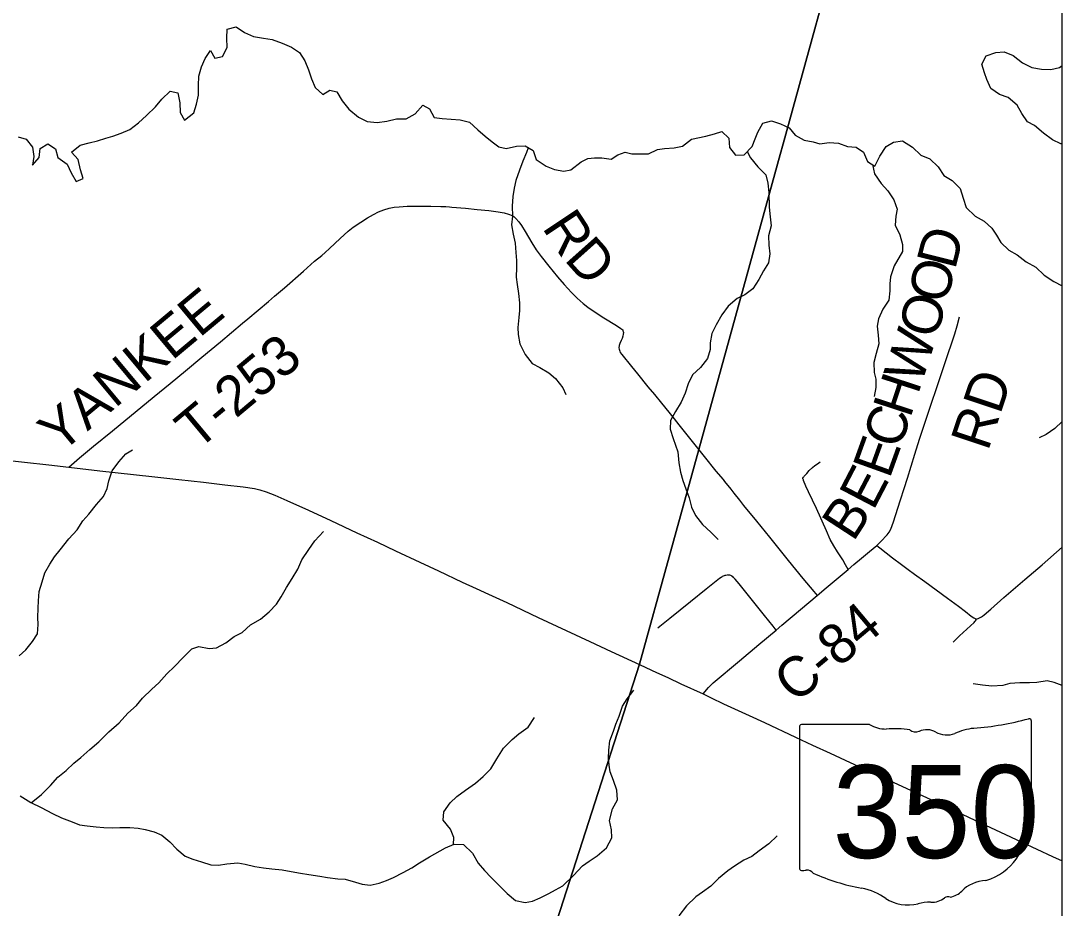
# Model space of a CAD drawing. Extents: x 0 to 34, y 0 to 22.
# Drawn here: x 22.483 to 23.962, y 16.521 to 17.781 of the extents above; entities that cross this region are included whole.
import ezdxf

# ---------------------------------------------------------------- set-up
doc = ezdxf.new("R2010")
doc.units = 0
for name, color, linetype in [('GM_X_Corporation', 7, 'Continuous'), ('GM_X_County_Road', 7, 'Continuous'), ('GM_X_County_Road_Text', 7, 'Continuous'), ('GM_X_Major_Lake', 7, 'Continuous'), ('GM_X_Minor_River', 7, 'Continuous'), ('GM_X_State_Location', 7, 'Continuous'), ('GM_X_State_Route', 7, 'Continuous'), ('GM_X_State_Shield', 7, 'Continuous'), ('GM_X_Township_Road', 7, 'Continuous'), ('GM_X_Township_Road_Text', 7, 'Continuous')]:
    doc.layers.add(name, color=color, linetype=linetype)

msp = doc.modelspace()

# ---------------------------------------------------------------- linework, layer by layer
at = {"layer": 'GM_X_Corporation'}
for points in [[(17.597, 14.3059), (23.9625, 14.3059), (23.9625, 21.1059), (18.23, 21.1059), (18.203, 20.7746), (18.1731, 20.4696), (18.0879, 19.5959), (18.0387, 19.0962), (17.9672, 18.2605), (17.8718, 17.2256), (17.7834, 16.317), (17.7373, 15.7617), (17.7239, 15.6245), (17.6136, 14.4601)], [(22.6629, 14.3059), (23.9625, 14.3059), (23.9625, 18.7666), (23.8567, 18.7798), (23.8507, 18.7519), (23.7107, 18.1304), (23.6615, 17.9524), (23.566, 17.6066), (23.5619, 17.5912), (23.4462, 17.1725), (23.362, 16.8676), (23.1639, 16.2517), (23.0409, 15.7041), (22.7103, 14.4966)]]:
    msp.add_lwpolyline(points, close=True, dxfattribs=at)
msp.add_lwpolyline([(23.1639, 16.2517), (23.362, 16.8676), (23.4462, 17.1725), (23.5619, 17.5912), (23.566, 17.6066), (23.6615, 17.9524), (23.7107, 18.1304), (23.8507, 18.7519), (23.8567, 18.7798), (23.8372, 18.7818), (22.8728, 18.8666), (22.8523, 19.0143), (22.5453, 19.0171), (22.4736, 19.0897), (21.6862, 19.7442)], dxfattribs=at)
at = {"layer": 'GM_X_County_Road'}
for points in [[(23.6991, 17.0361), (23.705, 17.0416), (23.7138, 17.0511), (23.7167, 17.055), (23.7189, 17.0593), (23.7228, 17.0697), (23.7293, 17.0891), (23.7329, 17.101), (23.7379, 17.117), (23.7426, 17.1318), (23.7531, 17.1656), (23.7599, 17.187), (23.7693, 17.2153), (23.7772, 17.2396), (23.7836, 17.2576), (23.7959, 17.2943), (23.8099, 17.3364), (23.8135, 17.348), (23.8169, 17.3606)], [(23.6584, 17.0021), (23.6667, 17.0091), (23.6777, 17.0182), (23.6886, 17.0275), (23.6991, 17.0361)], [(23.6145, 16.9653), (23.6271, 16.9759), (23.65, 16.9951), (23.6584, 17.0021)], [(23.5561, 16.9161), (23.5644, 16.9231), (23.5906, 16.9451), (23.6145, 16.9653)], [(23.4524, 16.8256), (23.4601, 16.8346), (23.467, 16.841), (23.504, 16.8723), (23.5315, 16.8956), (23.5561, 16.9161)]]:
    msp.add_lwpolyline(points, dxfattribs=at)
at = {"layer": 'GM_X_Major_Lake'}
for points in [[(22.4794, 17.6161), (22.491, 17.6128), (22.5001, 17.6015), (22.5017, 17.5882), (22.4998, 17.5761), (22.5096, 17.5868), (22.5111, 17.5997), (22.5219, 17.6066), (22.5327, 17.5995), (22.5361, 17.5869), (22.5491, 17.5774), (22.5548, 17.5651), (22.562, 17.5528), (22.572, 17.5574), (22.5682, 17.5697), (22.5648, 17.5842), (22.5556, 17.5947), (22.5677, 17.6046), (22.5803, 17.6076), (22.5925, 17.6107), (22.6043, 17.6142), (22.6139, 17.6173), (22.6257, 17.6216), (22.638, 17.6269), (22.6504, 17.636), (22.6617, 17.6467), (22.6749, 17.6589), (22.6839, 17.67), (22.6956, 17.6811), (22.7065, 17.6789), (22.7092, 17.6648), (22.7095, 17.6511), (22.7157, 17.6399), (22.7292, 17.6506), (22.733, 17.6626), (22.7356, 17.6754), (22.7356, 17.6891), (22.736, 17.7023), (22.7398, 17.7155), (22.7454, 17.7275), (22.753, 17.7387), (22.7591, 17.7279), (22.7698, 17.7302), (22.7766, 17.7433), (22.7762, 17.7566), (22.7766, 17.7691), (22.7892, 17.7726), (22.8011, 17.7647), (22.8138, 17.759), (22.8281, 17.7563), (22.8402, 17.7545), (22.8548, 17.7495), (22.8679, 17.7438), (22.8794, 17.7363), (22.887, 17.7243), (22.892, 17.7113), (22.8961, 17.6987), (22.9015, 17.6864), (22.9122, 17.6762), (22.9222, 17.6828), (22.9324, 17.6802), (22.9396, 17.6675), (22.9495, 17.6558), (22.9631, 17.6441), (22.9755, 17.638), (22.9894, 17.6365), (23.0035, 17.6384), (23.0169, 17.6418), (23.0309, 17.6418), (23.0436, 17.6491), (23.0542, 17.6613), (23.0639, 17.6561), (23.0703, 17.6438), (23.082, 17.6423)], [(23.9625, 17.6062), (23.9606, 17.6066), (23.9486, 17.6122), (23.936, 17.6217), (23.9231, 17.6323), (23.9134, 17.6378), (23.905, 17.6495), (23.8985, 17.6614), (23.886, 17.672), (23.8736, 17.6765), (23.8613, 17.6848), (23.8553, 17.6979), (23.8521, 17.7074), (23.8483, 17.7197), (23.8547, 17.7313), (23.8681, 17.7362), (23.8799, 17.737), (23.893, 17.7317), (23.9063, 17.7215), (23.9194, 17.7147), (23.9333, 17.7124), (23.9462, 17.7117), (23.9588, 17.7147), (23.9625, 17.7174)], [(23.082, 17.6423), (23.0945, 17.6416), (23.1074, 17.6405), (23.1205, 17.6371), (23.1327, 17.6261), (23.1427, 17.6175), (23.1527, 17.6092), (23.1623, 17.6021), (23.1729, 17.5996), (23.1874, 17.6033), (23.1999, 17.6034), (23.211, 17.597), (23.2156, 17.5843), (23.2297, 17.5745), (23.2413, 17.57), (23.2545, 17.5677), (23.2648, 17.5697), (23.2791, 17.5807), (23.2887, 17.5854), (23.2982, 17.5866), (23.3085, 17.5863), (23.3217, 17.5844), (23.3313, 17.5906), (23.3417, 17.5945), (23.3514, 17.5923), (23.3647, 17.592), (23.3749, 17.5924), (23.3876, 17.5982), (23.3975, 17.5998), (23.4112, 17.6005), (23.423, 17.6033), (23.4358, 17.6131), (23.4563, 17.6171), (23.4689, 17.6206), (23.4789, 17.6237), (23.4888, 17.6143), (23.49, 17.6014), (23.4987, 17.5902), (23.5109, 17.5906), (23.5222, 17.6028), (23.5263, 17.6133), (23.53, 17.6231), (23.5372, 17.6357), (23.5494, 17.6392), (23.5625, 17.635), (23.5745, 17.629), (23.5833, 17.6185), (23.5959, 17.6114), (23.6088, 17.6091), (23.6185, 17.6066), (23.6315, 17.6085), (23.6447, 17.6074), (23.6578, 17.6024), (23.6699, 17.6017), (23.6803, 17.5946), (23.686, 17.5815), (23.6964, 17.5748), (23.7033, 17.589), (23.7127, 17.6024), (23.7228, 17.6086), (23.7357, 17.6105), (23.7498, 17.6018), (23.7616, 17.5905), (23.7744, 17.5852), (23.7865, 17.5738), (23.7945, 17.5615), (23.8061, 17.5543), (23.8175, 17.543), (23.822, 17.5292), (23.8262, 17.5158), (23.8391, 17.5037), (23.8518, 17.4965), (23.8628, 17.4867), (23.8694, 17.4767), (23.8755, 17.4663), (23.8869, 17.4553), (23.8985, 17.4489), (23.9115, 17.4387), (23.9249, 17.4311), (23.9371, 17.4198), (23.9508, 17.4107), (23.9625, 17.405)]]:
    msp.add_lwpolyline(points, dxfattribs=at)
at = {"layer": 'GM_X_Minor_River'}
for points in [[(23.2041, 17.6009), (23.2018, 17.594), (23.1966, 17.5816), (23.1918, 17.5688), (23.1866, 17.5541), (23.1841, 17.5435), (23.1823, 17.5314), (23.1813, 17.5181), (23.1817, 17.5037), (23.1804, 17.4912), (23.1827, 17.4779), (23.1855, 17.4653), (23.1867, 17.452), (23.1873, 17.4406), (23.1874, 17.4308), (23.1872, 17.4171), (23.1885, 17.4065), (23.1901, 17.3939), (23.1917, 17.3806), (23.1915, 17.3696), (23.1909, 17.3598), (23.1891, 17.3454), (23.1897, 17.3355), (23.192, 17.3222), (23.1997, 17.3072), (23.2097, 17.2945), (23.2205, 17.289), (23.2332, 17.2811), (23.2429, 17.2734), (23.2533, 17.2599), (23.2576, 17.2503)], [(23.5153, 17.5954), (23.5199, 17.5866), (23.5302, 17.5738), (23.5417, 17.5626), (23.5445, 17.5504), (23.5457, 17.5371), (23.5461, 17.5166), (23.5477, 17.5029), (23.5493, 17.49), (23.5453, 17.476), (23.5457, 17.4627), (23.5474, 17.4502), (23.5456, 17.4373), (23.5382, 17.4261), (23.5315, 17.4137), (23.5229, 17.4006), (23.5117, 17.3921), (23.501, 17.387), (23.4883, 17.3759), (23.4793, 17.3635), (23.4711, 17.3496), (23.4647, 17.3369), (23.4626, 17.324), (23.4624, 17.3145), (23.4587, 17.3017), (23.449, 17.289), (23.4374, 17.2782), (23.4311, 17.2655), (23.427, 17.2523), (23.4214, 17.2395), (23.4132, 17.2264), (23.4061, 17.2136), (23.4055, 17.2011), (23.4098, 17.1881), (23.4168, 17.1691)], [(23.6933, 17.5769), (23.6959, 17.5637), (23.7055, 17.5499), (23.7148, 17.5395), (23.7236, 17.5268), (23.7279, 17.5138), (23.7262, 17.5039), (23.7251, 17.4911), (23.732, 17.4773), (23.7359, 17.4635), (23.7357, 17.4537), (23.7239, 17.433), (23.7187, 17.4176), (23.7177, 17.4074), (23.7179, 17.3975), (23.7161, 17.3846), (23.7079, 17.3715), (23.7016, 17.358), (23.6995, 17.3474), (23.7011, 17.3345), (23.702, 17.3223), (23.6983, 17.3087), (23.695, 17.2959), (23.6955, 17.2818), (23.6979, 17.2723), (23.698, 17.2602), (23.6955, 17.2477)], [(23.9625, 17.2122), (23.9522, 17.202), (23.9399, 17.1935), (23.9296, 17.1888)], [(22.481, 16.8793), (22.4906, 16.8879), (22.5002, 16.8999), (22.5072, 16.9108), (22.5082, 16.9241), (22.5076, 16.934), (22.5081, 16.9473), (22.5087, 16.9575), (22.5096, 16.9708), (22.5136, 16.9844), (22.5176, 16.9972), (22.5246, 17.0097), (22.5312, 17.0198), (22.5393, 17.03), (22.5517, 17.0454), (22.5632, 17.0581), (22.5717, 17.0709), (22.5798, 17.0807), (22.5907, 17.0942), (22.6007, 17.1058), (22.6062, 17.1171), (22.6086, 17.1281), (22.6133, 17.1421), (22.6226, 17.1549), (22.6327, 17.1661), (22.6422, 17.1717)], [(23.4168, 17.1691), (23.4181, 17.1535), (23.4206, 17.1402), (23.4238, 17.1284), (23.4278, 17.1166), (23.4325, 17.1036), (23.4362, 17.0906), (23.4417, 17.0788), (23.4517, 17.0658), (23.4637, 17.055), (23.4738, 17.0446)], [(22.498, 16.6709), (22.513, 16.6826), (22.5257, 16.6953), (22.5361, 16.7073), (22.5476, 16.7167), (22.5588, 16.7268), (22.5684, 16.735), (22.5814, 16.7466), (22.5941, 16.7574), (22.6083, 16.7713), (22.6233, 16.7844), (22.6356, 16.7982), (22.6479, 16.8091), (22.6564, 16.8192), (22.6695, 16.8319), (22.6795, 16.8413), (22.6907, 16.8537), (22.7018, 16.8645), (22.7141, 16.8769), (22.7265, 16.8896), (22.736, 16.8929), (22.7507, 16.8897), (22.7614, 16.891), (22.7747, 16.8977), (22.7866, 16.907), (22.7977, 16.9126), (22.8096, 16.9234), (22.8238, 16.9316), (22.836, 16.942), (22.8464, 16.9529), (22.853, 16.9631), (22.8608, 16.9766), (22.8686, 16.9894), (22.8767, 17.0026), (22.8826, 17.0158), (22.8923, 17.0305), (22.9008, 17.0425), (22.9132, 17.056)], [(23.9625, 16.8375), (23.9509, 16.8414), (23.941, 16.8438), (23.9266, 16.8414), (23.9163, 16.8411), (23.9023, 16.8413), (23.8883, 16.84), (23.878, 16.8371), (23.8628, 16.8365), (23.8492, 16.8379), (23.8363, 16.8396)], [(23.0496, 16.5853), (23.0638, 16.5942), (23.0867, 16.6068), (23.0989, 16.612), (23.1122, 16.6114), (23.1249, 16.5991), (23.133, 16.5849), (23.142, 16.5746), (23.1513, 16.5649), (23.1611, 16.5553), (23.1741, 16.5419), (23.1861, 16.5322), (23.1997, 16.5294), (23.2104, 16.5311), (23.2211, 16.5359), (23.2333, 16.5422), (23.2428, 16.547), (23.2532, 16.5529), (23.2682, 16.5675), (23.2813, 16.5814), (23.2908, 16.5877), (23.3019, 16.5955), (23.3154, 16.6067), (23.3228, 16.6211), (23.3226, 16.6325), (23.3197, 16.6458), (23.3238, 16.6621), (23.3308, 16.6749), (23.3298, 16.6885), (23.3251, 16.7023), (23.3207, 16.7149), (23.319, 16.7244), (23.318, 16.7339), (23.3185, 16.7456), (23.3199, 16.7589), (23.325, 16.7725), (23.3285, 16.7823), (23.3333, 16.7937), (23.338, 16.808), (23.3446, 16.8182), (23.3543, 16.8306)], [(23.098, 16.6116), (23.0983, 16.6215), (23.0936, 16.6333), (23.0831, 16.646), (23.0841, 16.6581), (23.093, 16.6709), (23.1026, 16.6795), (23.1152, 16.6888), (23.1294, 16.6985), (23.1401, 16.7082), (23.1509, 16.7191), (23.1595, 16.7334), (23.1688, 16.7484), (23.1811, 16.7604), (23.1907, 16.7686), (23.2041, 16.7783), (23.213, 16.7919)], [(22.4827, 16.6807), (22.4977, 16.671), (22.5124, 16.664), (22.5282, 16.6554), (22.5413, 16.6492), (22.5564, 16.6437), (22.5666, 16.6397), (22.5776, 16.6381), (22.5904, 16.6364), (22.6014, 16.6358), (22.6136, 16.6353), (22.6242, 16.6359), (22.6382, 16.6357), (22.6503, 16.6348), (22.6602, 16.6328), (22.6726, 16.6296), (22.6836, 16.6248), (22.6952, 16.6152), (22.7049, 16.6048), (22.7169, 16.5952), (22.7278, 16.5908), (22.7399, 16.5869), (22.7531, 16.5829), (22.7641, 16.582), (22.7759, 16.5841), (22.7914, 16.5854), (22.802, 16.5837), (22.8156, 16.5805), (22.8281, 16.5785), (22.8398, 16.5772), (22.8546, 16.5754), (22.8675, 16.573), (22.8807, 16.5709), (22.8924, 16.5689), (22.9083, 16.5667), (22.9189, 16.5647), (22.9337, 16.563), (22.9439, 16.5621), (22.9586, 16.5581), (22.9684, 16.5553), (22.9794, 16.5536), (22.9923, 16.5565), (23.0026, 16.5605), (23.0126, 16.5649), (23.0263, 16.5716), (23.0389, 16.5782), (23.0496, 16.5853)], [(23.5579, 16.6239), (23.546, 16.6127), (23.5322, 16.6026), (23.5215, 16.5944), (23.5104, 16.5893), (23.497, 16.5807), (23.4874, 16.574), (23.4744, 16.5632), (23.4636, 16.5523), (23.4517, 16.5441), (23.4421, 16.5374), (23.4287, 16.5247), (23.4182, 16.5104)]]:
    msp.add_lwpolyline(points, dxfattribs=at)
at = {"layer": 'GM_X_State_Route'}
for points in [[(22.454, 17.1582), (22.5231, 17.1504), (22.5517, 17.1472), (22.5954, 17.1423), (22.6695, 17.1342), (22.7078, 17.13), (22.743, 17.1259), (22.7732, 17.1224), (22.7991, 17.1193), (22.8151, 17.1169), (22.8231, 17.1152), (22.8321, 17.1124), (22.8443, 17.1077), (22.8614, 17.1002), (22.8918, 17.0861), (22.9235, 17.0717), (22.9607, 17.0543), (22.99, 17.0407), (23.0158, 17.0285), (23.0501, 17.0124), (23.0766, 17.0001), (23.1102, 16.984), (23.13, 16.975), (23.1475, 16.967), (23.1735, 16.955), (23.2184, 16.9338), (23.2578, 16.9154), (23.2917, 16.8999), (23.3221, 16.8857), (23.3623, 16.867)], [(23.3623, 16.867), (23.3633, 16.8666), (23.3864, 16.8558), (23.4022, 16.8486), (23.4207, 16.8398), (23.4524, 16.8256), (23.4641, 16.8196), (23.4816, 16.8115), (23.5177, 16.7949), (23.5396, 16.7846), (23.5835, 16.7641), (23.6078, 16.7528), (23.6331, 16.741), (23.6889, 16.7152), (23.7234, 16.6994), (23.7533, 16.6857), (23.7923, 16.6677), (23.8384, 16.6461), (23.9043, 16.6154), (23.9488, 16.5946), (23.9625, 16.5882)]]:
    msp.add_lwpolyline(points, dxfattribs=at)
at = {"layer": 'GM_X_State_Shield'}
for p, q in [((23.5893, 16.7784), (23.5893, 16.5783)), ((23.689, 16.7818), (23.5925, 16.7818)), ((23.9188, 16.6821), (23.9188, 16.7868)), ((23.9188, 16.6821), (23.9188, 16.6821))]:
    msp.add_line(p, q, dxfattribs=at)
for centre, major_axis, start_param, end_param in [((23.8014, 17.0547), (0.3495, 0), 4.814394, 5.042369), ((23.9152, 16.7872), (0.00367, 0), 6.141152, 7.989035), ((23.593, 16.7788), (0.00382, 0), 1.712693, 3.28349), ((23.712, 16.8051), (0.037, 0), 4.042523, 4.731795), ((23.7243, 16.6695), (0.133, 0), 1.404758, 1.657858), ((23.7545, 16.7799), (0.0107, 0), 3.836095, 5.185415), ((23.7702, 16.7567), (0.0222, 0), 0.950623, 2.079405), ((23.846, 16.7207), (0.0703, 0), 1.699011, 2.107814), ((23.7988, 16.7885), (0.0267, 0), 4.081561, 5.145723), ((23.918, 16.6744), (0.00568, 0), 1.883978, 3.671073), ((23.8819, 16.6612), (0.0341, 0), 5.934695, 6.695948), ((23.9149, 16.6817), (0.00393, 0), 5.05454, 6.418171), ((23.932, 16.6383), (0.0248, 0), 2.387724, 3.262537), ((23.821, 16.625), (0.0874, 0), 5.101752, 6.440018), ((23.5931, 16.5778), (0.00385, 0), 3.00124, 4.508301), ((23.5937, 16.5983), (0.0294, 0), 4.665946, 4.897461), ((23.5997, 16.5667), (0.0106, 0), 0.519207, 1.627899), ((23.7335, 16.7465), (0.2524, 0), 4.195997, 4.488961), ((23.8579, 16.5221), (0.0479, 0), 1.647645, 2.488434), ((23.6582, 16.4884), (0.079, 0), 0.823519, 1.323587), ((23.8004, 16.5314), (0.00752, 0), 1.147584, 2.315152), ((23.7972, 16.5589), (0.0282, 0), 4.937069, 5.64225), ((23.7437, 16.5657), (0.0501, 0), 4.026481, 4.996735), ((23.7726, 16.4966), (0.0412, 0), 1.495662, 1.94098), ((23.7763, 16.5508), (0.0267, 0), 4.691044, 5.507374)]:
    msp.add_ellipse(centre, major_axis=major_axis, ratio=0.8, start_param=start_param, end_param=end_param, dxfattribs=at)
at = {"layer": 'GM_X_Township_Road'}
for points in [[(22.8439, 17.3901), (22.8577, 17.402), (22.8848, 17.4258), (22.9007, 17.4397), (22.9108, 17.4479), (22.9155, 17.4519), (22.9218, 17.4578), (22.937, 17.4721), (22.9484, 17.4824), (22.9556, 17.4881), (22.9663, 17.4953), (22.9757, 17.5012), (22.9843, 17.5061), (22.9915, 17.5097), (22.9989, 17.5127), (23.0065, 17.5149), (23.0137, 17.5163), (23.021, 17.5171), (23.0321, 17.5177), (23.0525, 17.5179), (23.0612, 17.5179), (23.0656, 17.5178), (23.0798, 17.5175), (23.0873, 17.5172)], [(23.0873, 17.5172), (23.0921, 17.517), (23.0956, 17.5167), (23.1151, 17.515), (23.1317, 17.5133), (23.1483, 17.5116), (23.1612, 17.51), (23.1697, 17.5084), (23.1762, 17.5066), (23.1812, 17.5045), (23.1837, 17.503), (23.1866, 17.5002), (23.1908, 17.4957), (23.1947, 17.4902), (23.1999, 17.4818), (23.2093, 17.4658), (23.2156, 17.4558), (23.2224, 17.4462), (23.2332, 17.4325), (23.2455, 17.4177), (23.2553, 17.4065), (23.2654, 17.3955), (23.2738, 17.3871), (23.2822, 17.3796), (23.2886, 17.3746), (23.2977, 17.3681), (23.3113, 17.3593), (23.3294, 17.3485), (23.3356, 17.3444), (23.337, 17.3432), (23.3383, 17.3421), (23.3387, 17.3411), (23.3391, 17.3401), (23.3395, 17.3384)], [(22.8057, 17.3581), (22.8351, 17.3826), (22.8439, 17.3901)], [(22.5517, 17.1472), (22.5593, 17.1538), (22.5667, 17.1604), (22.5868, 17.177), (22.6137, 17.1991), (22.6727, 17.2476), (22.6953, 17.266), (22.7174, 17.2842), (22.7407, 17.3037), (22.7672, 17.3253), (22.7984, 17.352), (22.8057, 17.3581)], [(23.3395, 17.3384), (23.3391, 17.3362), (23.3385, 17.3334), (23.3373, 17.3299), (23.3359, 17.3271), (23.3341, 17.323), (23.3332, 17.3199), (23.333, 17.3166), (23.3333, 17.315), (23.3341, 17.3119), (23.3348, 17.3103), (23.3369, 17.3071), (23.3506, 17.2902), (23.3593, 17.2796), (23.3742, 17.2613), (23.3834, 17.2504), (23.3933, 17.2384), (23.4037, 17.2254), (23.4114, 17.2161), (23.418, 17.2076), (23.4352, 17.1859), (23.4464, 17.172)], [(23.4464, 17.172), (23.4541, 17.1624), (23.4708, 17.1417), (23.4808, 17.1296), (23.4829, 17.1271), (23.4917, 17.1163), (23.496, 17.1105), (23.5042, 17.1004), (23.51, 17.0931), (23.5284, 17.0704), (23.5467, 17.0477), (23.5734, 17.0149), (23.5941, 16.9894), (23.6098, 16.9708), (23.6145, 16.9653)], [(23.5942, 17.1319), (23.5951, 17.1333), (23.5955, 17.1338), (23.5962, 17.1346), (23.5996, 17.1385), (23.6033, 17.1425), (23.6079, 17.147), (23.6111, 17.1496), (23.6148, 17.1522), (23.6189, 17.155)], [(23.6584, 17.0021), (23.6548, 17.0086), (23.6508, 17.0156), (23.6434, 17.0271), (23.6381, 17.0355), (23.633, 17.0448), (23.6276, 17.0567), (23.6137, 17.0885), (23.6023, 17.1122), (23.5986, 17.1204), (23.5953, 17.1283), (23.5949, 17.1292), (23.5947, 17.1299), (23.5943, 17.1309), (23.5942, 17.1319)], [(23.6991, 17.0361), (23.7034, 17.0328), (23.7215, 17.0188), (23.7343, 17.0091), (23.7439, 17.002), (23.7527, 16.9952), (23.7674, 16.9848), (23.7994, 16.9613), (23.8152, 16.9498), (23.8252, 16.9425), (23.8334, 16.9359), (23.8371, 16.9333), (23.8387, 16.9326), (23.8408, 16.9316)], [(23.8408, 16.9316), (23.844, 16.9328), (23.8462, 16.9339), (23.8477, 16.9347), (23.8495, 16.9359), (23.8519, 16.9378), (23.8613, 16.9455), (23.8798, 16.9622), (23.9094, 16.988), (23.9339, 17.0086), (23.9625, 17.0335)], [(23.3883, 16.9191), (23.3911, 16.9215), (23.4052, 16.9328), (23.4347, 16.9565), (23.4568, 16.9746), (23.4732, 16.9878), (23.476, 16.9898), (23.4781, 16.9913), (23.4795, 16.9922), (23.4802, 16.9926), (23.4813, 16.9932), (23.4827, 16.9937), (23.4837, 16.9939), (23.485, 16.9941), (23.487, 16.9942)], [(23.5561, 16.9161), (23.5518, 16.9216), (23.5397, 16.9366), (23.5036, 16.9817), (23.4981, 16.9885), (23.4958, 16.9908), (23.4945, 16.9919), (23.4939, 16.9923), (23.4929, 16.9929), (23.492, 16.9934), (23.4903, 16.9939), (23.4885, 16.9941), (23.487, 16.9942)], [(23.8076, 16.8987), (23.8169, 16.9079), (23.8375, 16.9269), (23.8385, 16.928), (23.8392, 16.9289), (23.8402, 16.9304), (23.8408, 16.9316)]]:
    msp.add_lwpolyline(points, dxfattribs=at)

# ---------------------------------------------------------------- texts
at = {"layer": 'GM_X_County_Road_Text'}
for s, height, rotation, p in [('D', 0.0568, 75.879, (23.8103, 17.4264)), ('O', 0.0568, 75.653, (23.7978, 17.3777)), ('O', 0.0568, 73.7336, (23.7832, 17.3277)), ('W', 0.0568, 71.9832, (23.7623, 17.2633)), ('H', 0.0568, 71.8565, (23.7467, 17.2157)), ('RD', 0.05682, 71.5653, (23.8571, 17.1688)), ('C', 0.0568, 71.8744, (23.7322, 17.1713)), ('E', 0.0568, 70.1861, (23.7172, 17.1296)), ('E', 0.0568, 62.4246, (23.6941, 17.0843)), ('B', 0.0568, 56.947, (23.6657, 17.04)), ('C-84', 0.05682, 39.9785, (23.5837, 16.8104))]:
    msp.add_text(s, height=height, rotation=rotation, dxfattribs=at).set_placement(p)
at = {"layer": 'GM_X_State_Location'}
for s in ['s', 'r']:
    msp.add_text(s, height=0.000189, dxfattribs=at).set_placement((23.7503, 16.665))
msp.add_text('350', height=0.000189, rotation=0, dxfattribs=at).set_placement((23.6835, 16.6513))
at = {"layer": 'GM_X_State_Shield'}
msp.add_text('350', height=0.13184, dxfattribs=at).set_placement((23.6362, 16.5924))
at = {"layer": 'GM_X_Township_Road_Text'}
for s, height, rotation, p in [('R', 0.0568, 303.6083, (23.2229, 17.4876)), ('D', 0.0568, 311.7166, (23.254, 17.442)), ('YANKEE', 0.05682, 39.8054, (22.5391, 17.1653)), ('T-253', 0.05682, 39.8409, (22.7337, 17.1698))]:
    msp.add_text(s, height=height, rotation=rotation, dxfattribs=at).set_placement(p)

doc.saveas('drawing.dxf')
